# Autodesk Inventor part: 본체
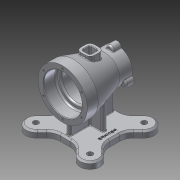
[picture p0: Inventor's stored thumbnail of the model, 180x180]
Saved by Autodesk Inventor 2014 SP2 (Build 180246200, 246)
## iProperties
Created: 2018-03
Part Number: 본체
Material: 알루미늄 6061
Document SubType Name: Modeling
Designer: 거성
Density: 2.71 g/cm^3
Appearance: 알루미늄 - 평지
Mass: 1028.95 g
Surface Area: 866.354 cm^2
Volume: 379.688 cm^3
Author: 거성
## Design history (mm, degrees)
sketch "스케치1" dims "d0" = 140
  geometry: L1 (0, 0)-(-49.497, 49.497); L2 (0, 0)-(-49.497, -49.497); L3 (0, 0)-(-70, 0); L4 (-35.239, 60.483)-(-19.755, 45); L5 (-60.483, 35.239)-(-45, 19.755); L6 (-19.755, -45)-(19.755, -45); L7 (45, -19.755)-(45, 19.755); L8 (19.755, 45)-(-19.755, 45); L9 (-45, 19.755)-(-45, -19.755); L10 (-45, -45)-(45, 45); L11 (49.497, -49.497)-(-45, 45); L12 (-35.239, -60.483)-(-19.755, -45); L13 (-60.483, -35.239)-(-45, -19.755); L14 (0, 0)-(54.385, 54.385); L15 (0, 0)-(70, 0); L16 (0, 0)-(60.568, -60.568); L17 (35.239, 60.483)-(19.755, 45); L18 (60.483, 35.239)-(45, 19.755); L19 (60.483, -35.239)-(45, -19.755); L20 (35.239, -60.483)-(19.755, -45); A1 r 18 centre (-49.497, -49.497) between (-60.483, -35.239) and (-35.239, -60.483); A2 r 18 centre (49.497, -49.497) between (35.239, -60.483) and (60.483, -35.239); A3 r 18 centre (-49.497, 49.497) between (-35.239, 60.483) and (-60.483, 35.239); A4 r 18 centre (49.497, 49.497) between (60.483, 35.239) and (35.239, 60.483); 1 further point
  constraints: 40 end point, 8 point on circle, 6 parallel, 6 perpendicular, 4 centre point, 4 point on line, 2 coincident, 2 horizontal, 1 midpoint, 16 other
  dimensions: "d1" = 45 deg angle of L3 L1; "d2" = 45 deg angle of L2 L3; "d4" = 18 radius of A1; "d5" = 90 distance between parallel lines of L6 L8; "d6" = 90 distance between parallel lines of L7 L9; "d7" = 45 deg angle of L15 L14; "d10" = 45 deg angle of L15 L16; "d11" = 18 radius of A2
extrude "돌출1" new body sketch "스케치1" distance "d12" = 12; taper "d13" = 0 deg
sketch "스케치2"
  geometry: L1 (82, 50)-(82, -50); L2 (0, -19.755)-(0, 19.755) reference; L3 (82, -50)-(109.5, -50); L4 (82, 50)-(127, 50); L5 (127, 50)-(127, 30); L6 (127, 30)-(109.5, -27); L7 (109.5, -27)-(109.5, -50); 3 further points
  constraints: 12 end point, 3 perpendicular, 2 midpoint, 1 horizontal alignment, 1 parallel, 1 vertical
  dimensions: "d14" = 82 distance between parallel lines of L1 L2; "d15" = 100 distance of L1.start L1.end; "d16" = 90 diameter of L5 L1; "d17" = 55 diameter of L7 L1; "d18" = 20 distance from line of L5.end L4; "d19" = 77 distance from line of L6.end L4
revolve "회전1" sketch "스케치2" stored, may be unused: angle "d20" = 90 deg
hole "구멍1" diameter "d23" = 70; stored, may be unused: countersink angle "d27" = 90 deg, drill point angle "d29" = 0 deg; dims "d21" = 10, "d22" = 10, "d24" = 6, "d25" = 4, "d26" = 2, "d28" = 23
hole "구멍2" diameter "d32" = 52; stored, may be unused: countersink angle "d36" = 90 deg, drill point angle "d38" = 0 deg; dims "d30" = 10, "d31" = 10, "d33" = 6, "d34" = 4, "d35" = 2, "d37" = 47
hole "구멍3" diameter "d41" = 40; stored, may be unused: countersink angle "d45" = 90 deg, drill point angle "d47" = 0 deg; dims "d39" = 10, "d40" = 10, "d42" = 6, "d43" = 4, "d44" = 2, "d46" = 30
sketch "스케치3"
  geometry: C1 r 20 at (0, 0) reference; A1 r 27.5 centre (0, 0) between (0, 27.5) and (-6.943, 26.609) reference; A2 r 7 centre (0, 27.5) between (6.943, 26.609) and (-6.943, 26.609); 1 further point
  constraints: 5 point on circle, 1 centre point, 1 vertical alignment
  dimensions: "d48" = 7 radius of A2
extrude "돌출2" join sketch "스케치3" distance "d49" = 15; taper "d50" = 0 deg
sketch "스케치4" dims "d54" = 80
  geometry: C1 r 35 at (0, 0) reference; C2 r 45 at (0, 0) reference; 3 further points
  constraints: 2 vertical alignment, 1 coincident, 2 other
hole "구멍4" sketch "스케치4" at (0, 40) diameter "d55" = 3.242; stored, may be unused: countersink angle "d59" = 90 deg, drill point angle "d61" = 118 deg; dims "d56" = 9, "d57" = 4, "d58" = 2, "d60" = 11
sketch "스케치5"
  geometry: A1 r 7 centre (-23.816, -41.25) between (-26.516, -34.792) and (-19.573, -46.817) reference; A2 r 7 centre (0, 0) between (6.943, -0.891) and (-6.943, -0.891) reference; A3 r 27.5 centre (0, -27.5) between (-6.943, -0.891) and (-26.516, -34.792) reference; 4 further points
  constraints: 2 coincident, 1 point on circle
hole "구멍5" sketch "스케치5" at (0, 0), (-23.816, -41.25), (23.779, -41.314) diameter "d65" = 3.242; stored, may be unused: countersink angle "d69" = 90 deg, drill point angle "d71" = 118 deg; dims "d66" = 9, "d67" = 4, "d68" = 2, "d70" = 11
node "작업 평면1"
sketch "스케치7"
  geometry: L1 (12.5, -12.5)-(-12.5, -12.5); L2 (-12.5, -12.5)-(-12.5, 12.5); L3 (-12.5, 12.5)-(12.5, 12.5); L4 (12.5, 12.5)-(12.5, -12.5); L5 (12.5, -12.5)-(-12.5, 12.5); L6 (-12.5, -12.5)-(12.5, 12.5); 1 further point
  constraints: 12 end point, 2 midpoint, 2 parallel, 1 horizontal, 1 perpendicular
  dimensions: "d73" = 25 distance between parallel lines of L4 L2; "d74" = 25 distance between parallel lines of L1 L3
extrude "돌출3" join sketch "스케치7" stored distance "d75" = 15; taper "d76" = 0 deg
sketch "스케치8"
  geometry: L1 (7.5, -7.5)-(-7.5, -7.5); L2 (-7.5, -7.5)-(-7.5, 7.5); L3 (-7.5, 7.5)-(7.5, 7.5); L4 (7.5, 7.5)-(7.5, -7.5); L5 (7.5, -7.5)-(-7.5, 7.5); L6 (-7.5, -7.5)-(7.5, 7.5); 1 further point
  constraints: 12 end point, 2 midpoint, 2 parallel, 1 horizontal, 1 perpendicular
  dimensions: "d77" = 15 distance between parallel lines of L4 L2; "d78" = 15 distance between parallel lines of L1 L3
extrude "돌출4" cut sketch "스케치8" distance "d79" = 30; taper "d80" = 0 deg
sketch "스케치9"
  geometry: L1 (-19.755, -45)-(19.755, -45) reference; L2 (0, -37)-(0, 37); L3 (-4, -37)-(-4, 37); L4 (4, 37)-(4, -37); A1 r 4 centre (0, -37) between (-4, -37) and (4, -37); A2 r 4 centre (0, 37) between (4, 37) and (-4, 37); 3 further points
  constraints: 8 end point, 4 point on circle, 4 tangent, 2 centre point, 2 coincident, 1 midpoint, 1 parallel, 1 perpendicular
  dimensions: "d81" = 74 distance of L2.start L2.end; "d82" = 4 radius of A2
extrude "돌출5" join sketch "스케치9" stored distance "d85" = 30; taper "d86" = 0 deg
sketch "스케치10"
  geometry: L1 (19.755, 45)-(-19.755, 45) reference; L2 (-24, 0)-(24, 0); L3 (-24, -4)-(24, -4); L4 (24, 4)-(-24, 4); A1 r 4 centre (-24, 0) between (-24, 4) and (-24, -4); A2 r 4 centre (24, 0) between (24, -4) and (24, 4); 1 further point
  constraints: 8 end point, 4 point on circle, 4 tangent, 2 centre point, 2 parallel, 1 midpoint
  dimensions: "d87" = 48 distance of L2.end L2.start; "d88" = 4 radius of A2
extrude "돌출6" join sketch "스케치10" stored distance "d89" = 30; taper "d90" = 0 deg
fillet "모깎기1" dims "d91" = 8
fillet "모깎기2" dims "d92" = 3
chamfer "모따기1" distance "d93" = 1; stored, may be unused: second distance "d94" = 2, angle "d95" = 45 deg
fillet "모깎기3" dims "d96" = 1
fillet "모깎기4" dims "d97" = 25
chamfer "모따기2" distance "d98" = 3; stored, may be unused: second distance "d99" = 2, angle "d100" = 45 deg
chamfer "모따기3" distance "d101" = 3; stored, may be unused: second distance "d102" = 2, angle "d103" = 45 deg
chamfer "모따기4" distance "d104" = 3; stored, may be unused: second distance "d105" = 2, angle "d106" = 45 deg
chamfer "모따기5" distance "d107" = 3; stored, may be unused: second distance "d108" = 2, angle "d109" = 45 deg
chamfer "모따기6" distance "d110" = 3; stored, may be unused: second distance "d111" = 2, angle "d112" = 45 deg
chamfer "모따기7" distance "d113" = 3; stored, may be unused: second distance "d114" = 2, angle "d115" = 45 deg
chamfer "모따기8" distance "d116" = 3; stored, may be unused: second distance "d117" = 2, angle "d118" = 45 deg
fillet "모깎기5" dims "d119" = 1
fillet "모깎기6" dims "d120" = 3
fillet "모깎기7" dims "d121" = 3
fillet "모깎기8" dims "d122" = 3
fillet "모깎기9" dims "d123" = 3
fillet "모깎기10" dims "d124" = 3
fillet "모깎기11" dims "d125" = 3
chamfer "모따기9" distance "d126" = 1; stored, may be unused: second distance "d127" = 2, angle "d128" = 45 deg
chamfer "모따기10" distance "d129" = 1; stored, may be unused: second distance "d130" = 2, angle "d131" = 45 deg
fillet "모깎기12" dims "d132" = 3
fillet "모깎기13" dims "d133" = 1
hole "구멍6" diameter "d136" = 10; stored, may be unused: countersink angle "d140" = 90 deg, drill point angle "d142" = 118 deg; dims "d134" = 10, "d135" = 10, "d137" = 9, "d138" = 4, "d139" = 2, "d141" = 11
hole "구멍7" diameter "d145" = 10; stored, may be unused: countersink angle "d149" = 90 deg, drill point angle "d151" = 118 deg; dims "d143" = 10, "d144" = 10, "d146" = 9, "d147" = 4, "d148" = 2, "d150" = 11
hole "구멍8" diameter "d154" = 10; stored, may be unused: countersink angle "d158" = 90 deg, drill point angle "d160" = 118 deg; dims "d152" = 10, "d153" = 10, "d155" = 9, "d156" = 4, "d157" = 2, "d159" = 11
hole "구멍9" diameter "d163" = 10; stored, may be unused: countersink angle "d167" = 90 deg, drill point angle "d169" = 118 deg; dims "d161" = 10, "d162" = 10, "d164" = 9, "d165" = 4, "d166" = 2, "d168" = 11
fillet "모깎기14" dims "d170" = 3
fillet "모깎기15" dims "d171" = 1
fillet "모깎기16" dims "d172" = 3
fillet "모깎기17" dims "d173" = 1
sketch "스케치11"
  geometry: L1 (32.5, -20.5)-(32.5, 14.5); L2 (32.5, 14.5)-(37.5, 14.5); L3 (37.5, 14.5)-(37.5, -20.5); L4 (37.5, -20.5)-(32.5, -20.5); L5 (35, -20.5)-(35, 14.5); L6 (32.5, -3)-(37.5, -3); 2 further points
  constraints: 4 end point, 4 midpoint, 2 other
  dimensions: "d174" = 5 distance between parallel lines of L3 L1; "d175" = 35 distance between parallel lines of L2 L4; "d176" = 35 distance from line of L5 point (0, 0); "d177" = 45 distance from line of point (0, 42) L6
feature "엠보싱1" sketch "스케치11" dims "d0" = 140, "d1" = 45 deg, "d2" = 45 deg, "d4" = 18, "d5" = 90, "d6" = 90, "d7" = 45 deg, "d10" = 45 deg, "d11" = 18, "d178" = 0.5, "d179" = 0
node "솔리드1"
pattern_circular "원형 패턴1" dims angle "d52" = 360 deg
pattern_circular "원형 패턴2" dims angle "d63" = 360 deg
other parameters: "d3" = 18, "d9" = 18, "d72" = 127
